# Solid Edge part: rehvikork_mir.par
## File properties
Author: KULL
Template: Iso Metric Part.par
Last saved by: KULL
Revision: 2
Application: Solid Edge
Accuracy: 0,990
Username: KULL
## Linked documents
rehvikork.par
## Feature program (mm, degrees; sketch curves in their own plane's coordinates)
part copy "CopiedPart_1"
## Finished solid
Body 1: solid body, 93 faces, 217 edges, 128 vertices.
  Faces by surface: blend 40, spline 40, sphere 6, torus 3, cylinder 2, cone 1, plane 1
  Edges by curve: intersection 128, circle 49, line 40
Bounding box of the edges (mm; curved faces can reach further): 4.951 x 16.000 x 16.000, from (-4, -8, -8) to (0.951, 8, 8).
Cylindrical faces by radius (mm): R7 x1, R8 x1
Conical faces (half-angle, radius in mm at the cone's reference point): 11.8765 deg R7 x1
Toroidal faces (ring radius, tube radius in mm): R7.0618 r0.08 x1, R7.6 r0.4 x1, R7.92 r0.08 x1
Spherical faces by radius (mm): R33.0132 x1, R33.5132 x2, R34.0132 x3
Planar faces by outward normal: -x 1
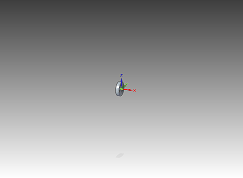
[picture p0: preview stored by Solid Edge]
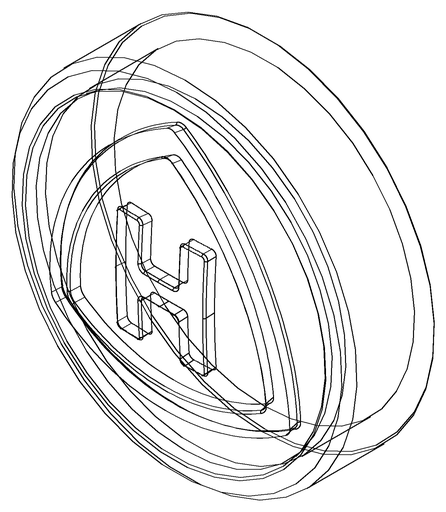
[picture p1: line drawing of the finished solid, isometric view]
